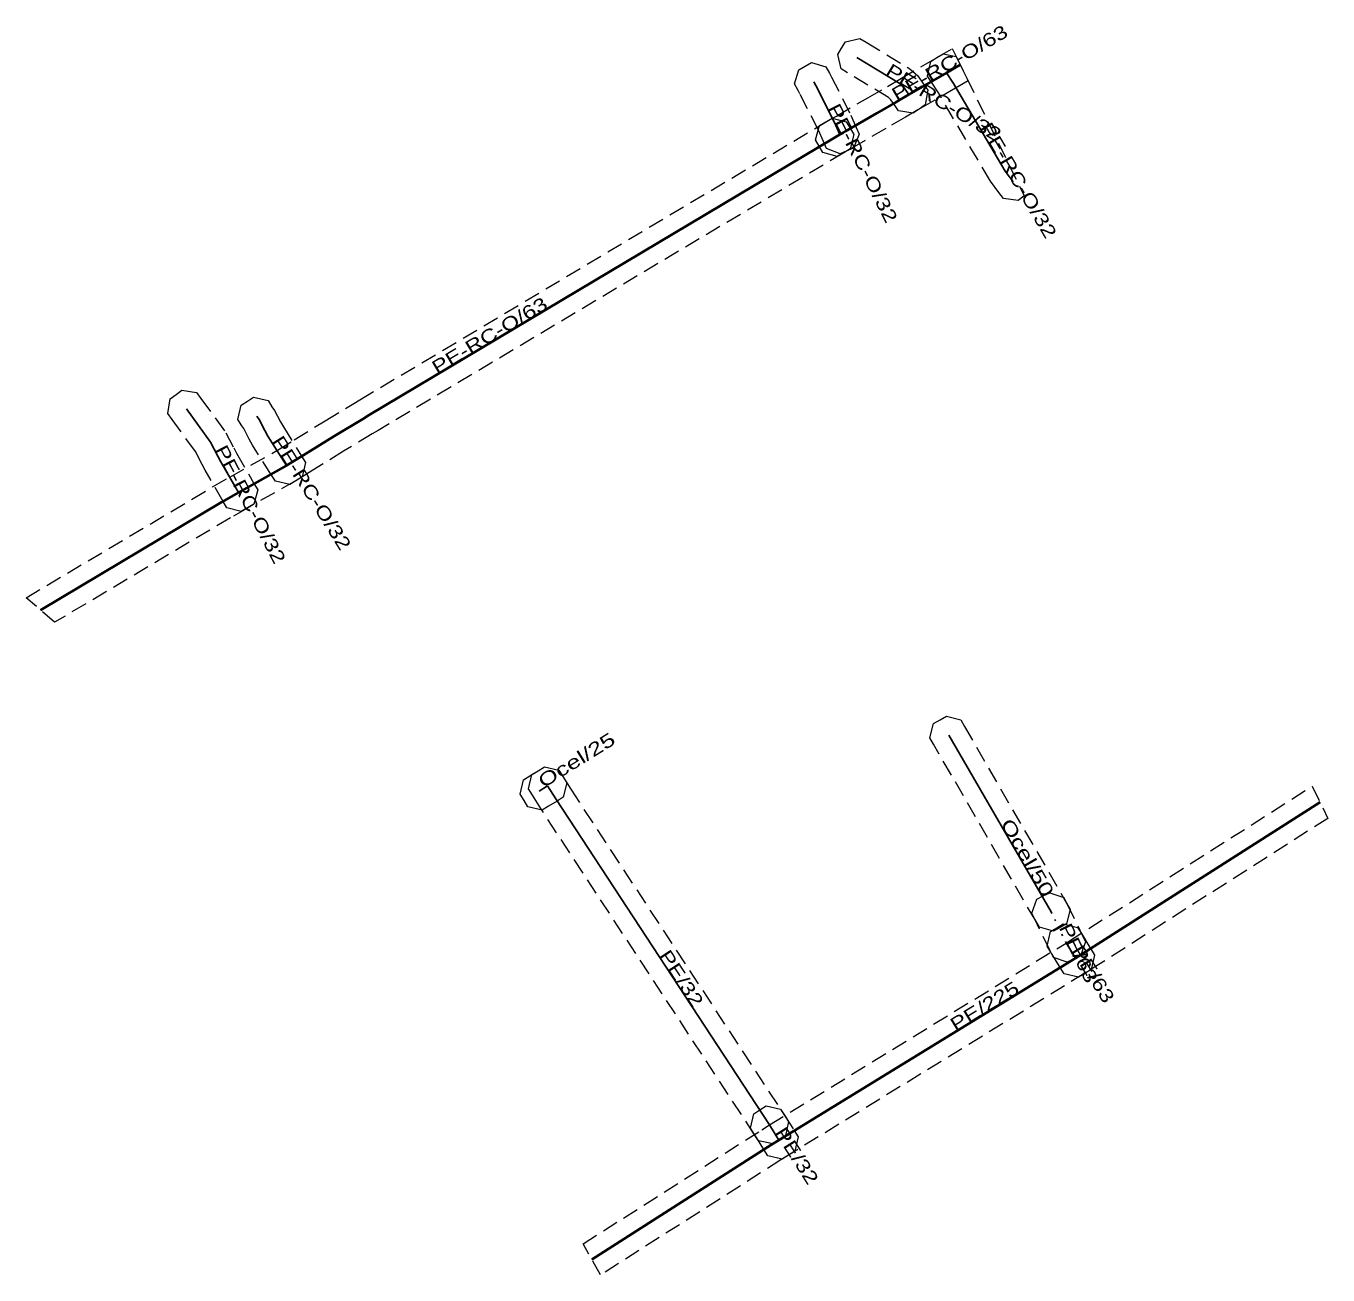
# Model space of a CAD drawing. Extents: x -571211 to -571138, y -1087087 to -1087016.9.
import ezdxf

# ---------------------------------------------------------------- set-up
doc = ezdxf.new("R2010")
doc.units = 0
doc.header["$LTSCALE"] = 0.3
doc.linetypes.add('DOTTED', pattern=[1.5, 0.3, -1.2])
doc.linetypes.add('MEDIUM_DASHED', pattern=[4.5, 3, -1.5])
for name, color, linetype, lineweight in [('1', 7, 'MEDIUM_DASHED', 13), ('24', 7, 'Continuous', 25), ('28', 7, 'DOTTED', 25)]:
    doc.layers.add(name, color=color, linetype=linetype, lineweight=lineweight)
doc.layers.add('30', color=7, linetype='Continuous')

msp = doc.modelspace()

# ---------------------------------------------------------------- linework, layer by layer
at = {"layer": '1'}
for points in [[(-571162.08, -1087021.684), (-571162.318, -1087021.345), (-571162.513, -1087021.068), (-571162.649, -1087020.946), (-571164.939, -1087019.555), (-571165.293, -1087019.34), (-571165.49, -1087018.535), (-571165.275, -1087018.181), (-571165.06, -1087017.827), (-571164.255, -1087017.63), (-571163.901, -1087017.845), (-571161.451, -1087019.334), (-571161.007, -1087019.732), (-571160.682, -1087020.195), (-571160.444, -1087020.534), (-571160.586, -1087021.35), (-571160.925, -1087021.588), (-571161.264, -1087021.826)], [(-571159.894, -1087018.686), (-571159.068, -1087018.2), (-571158.188, -1087020.004), (-571158.886, -1087020.414), (-571160.997, -1087021.634), (-571161.696, -1087022.044), (-571162.797, -1087022.684), (-571164.574, -1087023.718), (-571164.709, -1087023.794), (-571164.894, -1087023.895), (-571165.166, -1087024.05), (-571165.526, -1087024.254), (-571166.325, -1087024.034), (-571166.53, -1087023.674), (-571166.734, -1087023.314), (-571166.514, -1087022.515), (-571166.154, -1087022.31), (-571165.866, -1087022.147), (-571165.677, -1087022.044), (-571165.566, -1087021.982), (-571163.803, -1087020.956), (-571162.704, -1087020.316), (-571162.003, -1087019.906)], [(-571158.851, -1087018.644), (-571155.037, -1087026.46), (-571155.05, -1087026.47), (-571155.381, -1087026.719), (-571156.201, -1087026.601), (-571156.45, -1087026.27), (-571156.933, -1087025.626), (-571159.852, -1087020.684), (-571160.233, -1087020.089), (-571160.456, -1087019.74), (-571160.278, -1087018.93), (-571159.929, -1087018.707), (-571159.58, -1087018.484)], [(-571166.164, -1087019.215), (-571165.964, -1087019.578), (-571165.846, -1087019.793), (-571164.764, -1087021.925), (-571164.462, -1087022.624), (-571164.298, -1087023.004), (-571164.603, -1087023.775), (-571164.983, -1087023.939), (-571165.363, -1087024.103), (-571166.134, -1087023.798), (-571166.298, -1087023.418), (-571166.576, -1087022.775), (-571167.614, -1087020.727), (-571167.716, -1087020.542), (-571167.916, -1087020.179), (-571167.685, -1087019.384), (-571167.322, -1087019.184), (-571166.959, -1087018.984)], [(-571209.415, -1087050.378), (-571211.019, -1087049.003), (-571200.556, -1087042.787), (-571199.595, -1087042.231), (-571196.919, -1087040.729), (-571195.987, -1087040.15), (-571194.251, -1087039.076), (-571192.637, -1087038.104), (-571192.305, -1087037.903), (-571166.172, -1087022.321), (-571165.816, -1087022.109), (-571165.013, -1087022.312), (-571164.801, -1087022.668), (-571164.589, -1087023.024), (-571164.792, -1087023.827), (-571165.148, -1087024.039), (-571191.275, -1087039.617), (-571191.603, -1087039.816), (-571193.209, -1087040.784), (-571194.933, -1087041.85), (-571195.901, -1087042.451), (-571198.605, -1087043.969), (-571199.544, -1087044.513)], [(-571199.758, -1087043.959), (-571199.966, -1087043.6), (-571200.978, -1087041.85), (-571201.148, -1087041.52), (-571201.523, -1087040.797), (-571202.829, -1087038.997), (-571203.073, -1087038.662), (-571202.943, -1087037.844), (-571202.607, -1087037.601), (-571202.272, -1087037.357), (-571201.454, -1087037.487), (-571201.211, -1087037.823), (-571199.817, -1087039.743), (-571199.372, -1087040.6), (-571199.222, -1087040.89), (-571198.234, -1087042.6), (-571198.027, -1087042.958), (-571198.241, -1087043.758), (-571198.6, -1087043.966), (-571198.958, -1087044.173)], [(-571197.037, -1087042.472), (-571197.257, -1087042.121), (-571198.313, -1087040.436), (-571198.498, -1087040.098), (-571198.813, -1087039.515), (-571198.915, -1087039.354), (-571199.136, -1087039.004), (-571198.954, -1087038.196), (-571198.604, -1087037.975), (-571198.254, -1087037.754), (-571197.446, -1087037.936), (-571197.225, -1087038.286), (-571197.087, -1087038.505), (-571196.742, -1087039.142), (-571196.587, -1087039.424), (-571195.563, -1087041.059), (-571195.343, -1087041.41), (-571195.528, -1087042.217), (-571195.879, -1087042.437), (-571196.23, -1087042.657)], [(-571158.598, -1087055.86), (-571158.39, -1087056.219), (-571152.661, -1087066.129), (-571152.454, -1087066.487), (-571152.668, -1087067.287), (-571153.027, -1087067.495), (-571153.385, -1087067.702), (-571154.185, -1087067.488), (-571154.393, -1087067.129), (-571160.122, -1087057.219), (-571160.329, -1087056.861), (-571160.115, -1087056.061), (-571159.756, -1087055.853), (-571159.398, -1087055.646)], [(-571180.885, -1087060.186), (-571181.237, -1087060.404), (-571181.711, -1087060.698), (-571182.063, -1087060.916), (-571182.87, -1087060.727), (-571183.088, -1087060.375), (-571183.306, -1087060.023), (-571183.117, -1087059.216), (-571182.765, -1087058.998), (-571182.291, -1087058.704), (-571181.939, -1087058.486), (-571181.132, -1087058.675), (-571180.914, -1087059.027), (-571180.696, -1087059.379)], [(-571181.133, -1087058.675), (-571180.914, -1087059.027), (-571180.469, -1087059.744), (-571168.488, -1087078.027), (-571168.261, -1087078.373), (-571168.429, -1087079.184), (-571168.776, -1087079.411), (-571169.122, -1087079.638), (-571169.933, -1087079.47), (-571170.16, -1087079.123), (-571182.155, -1087060.82), (-571182.614, -1087060.081), (-571182.832, -1087059.729), (-571182.643, -1087058.923), (-571182.291, -1087058.704), (-571181.939, -1087058.486)], [(-571168.681, -1087080.537), (-571178.791, -1087086.99), (-571179.779, -1087085.248), (-571169.757, -1087078.851), (-571169.321, -1087078.572), (-571152.691, -1087068.373), (-571152.554, -1087068.285), (-571138.882, -1087059.568), (-571138, -1087061.377), (-571151.476, -1087069.969), (-571151.629, -1087070.067), (-571168.259, -1087080.268)], [(-571152.808, -1087065.82), (-571152.627, -1087066.192), (-571151.783, -1087067.931), (-571151.602, -1087068.304), (-571151.874, -1087069.087), (-571152.246, -1087069.268), (-571152.619, -1087069.449), (-571153.402, -1087069.177), (-571153.583, -1087068.805), (-571154.427, -1087067.066), (-571154.608, -1087066.693), (-571154.336, -1087065.91), (-571153.964, -1087065.729), (-571153.591, -1087065.548)], [(-571152.795, -1087070.096), (-571153.012, -1087069.743), (-571153.535, -1087068.891), (-571153.752, -1087068.538), (-571153.559, -1087067.733), (-571153.206, -1087067.516), (-571152.853, -1087067.299), (-571152.048, -1087067.492), (-571151.831, -1087067.845), (-571151.308, -1087068.697), (-571151.091, -1087069.05), (-571151.284, -1087069.855), (-571151.637, -1087070.072), (-571151.99, -1087070.289)], [(-571169.414, -1087080.304), (-571169.635, -1087079.954), (-571170.169, -1087079.109), (-571170.391, -1087078.759), (-571170.208, -1087077.951), (-571169.858, -1087077.73), (-571169.508, -1087077.508), (-571168.7, -1087077.691), (-571168.479, -1087078.041), (-571167.945, -1087078.886), (-571167.723, -1087079.236), (-571167.906, -1087080.044), (-571168.256, -1087080.265), (-571168.606, -1087080.487)]]:
    msp.add_lwpolyline(points, close=True, dxfattribs=at)
at = {"layer": '24'}
for p, q in [((-571159.256, -1087056.719), (-571153.527, -1087066.629)), ((-571181.764, -1087059.554), (-571182.238, -1087059.848)), ((-571152.16, -1087069.22), (-571152.683, -1087068.368)), ((-571168.79, -1087079.42), (-571169.324, -1087078.575))]:
    msp.add_line(p, q, dxfattribs=at)
at = {"layer": '24', "lineweight": 40}
for points in [[(-571158.628, -1087019.102), (-571159.39, -1087019.55), (-571161.5, -1087020.77), (-571162.2, -1087021.18), (-571163.3, -1087021.82), (-571165.07, -1087022.85), (-571165.193, -1087022.919), (-571165.38, -1087023.021), (-571165.66, -1087023.18)], [(-571165.66, -1087023.18), (-571191.79, -1087038.76), (-571192.12, -1087038.96), (-571193.73, -1087039.93), (-571195.46, -1087041), (-571196.41, -1087041.59), (-571199.1, -1087043.1), (-571200.05, -1087043.65), (-571210.217, -1087049.691)], [(-571138.441, -1087060.473), (-571152.015, -1087069.127), (-571152.16, -1087069.22), (-571168.79, -1087079.42), (-571169.219, -1087079.694), (-571179.285, -1087086.119)]]:
    msp.add_lwpolyline(points, dxfattribs=at)
at = {"layer": '24'}
for points in [[(-571161.5, -1087020.77), (-571161.76, -1087020.4), (-571162.05, -1087020.14), (-571164.42, -1087018.7)], [(-571159.39, -1087019.55), (-571159, -1087020.16), (-571156.1, -1087025.07), (-571155.65, -1087025.67)], [(-571166.84, -1087020.06), (-571166.73, -1087020.26), (-571165.67, -1087022.35), (-571165.38, -1087023.021)], [(-571199.1, -1087043.1), (-571200.1, -1087041.37), (-571200.26, -1087041.06), (-571200.67, -1087040.27), (-571202.02, -1087038.41)], [(-571196.41, -1087041.59), (-571197.45, -1087039.93), (-571197.62, -1087039.62), (-571197.95, -1087039.01), (-571198.07, -1087038.82)], [(-571181.764, -1087059.554), (-571181.312, -1087060.282), (-571169.324, -1087078.575)]]:
    msp.add_lwpolyline(points, dxfattribs=at)
at = {"layer": '28'}
msp.add_line((-571153.527, -1087066.629), (-571152.683, -1087068.368), dxfattribs=at)

# ---------------------------------------------------------------- texts
at = {"layer": '30'}
for s, rotation, width, p in [('PE-RC-O/63', 30.358, 1.3, (-571162.185, -1087021.171)), ('PE-RC-O/32', 328.717, 1.3, (-571162.875, -1087019.638)), ('PE-RC-O/32', 296.893, 1.3, (-571166.086, -1087021.529)), ('PE-RC-O/32', 300.567, 1.3, (-571157.543, -1087022.626)), ('PE-RC-O/63', 30.805, 1.3, (-571187.97, -1087036.482)), ('PE-RC-O/32', 302.067, 1.3, (-571197.267, -1087040.221)), ('PE-RC-O/32', 297.429, 1.3, (-571200.454, -1087040.686)), ('Ocel/25', 31.809, 1.4, (-571182.001, -1087059.701)), ('Ocel/50', 300.032, 1.4, (-571156.391, -1087061.674)), ('PE/63', 295.889, 1.3, (-571153.105, -1087067.498)), ('PE/32', 303.238, 1.3, (-571175.553, -1087069.07)), ('PE/63', 301.544, 1.3, (-571152.421, -1087068.794)), ('PE/225', 31.523, 1.3, (-571158.89, -1087073.347)), ('PE/32', 302.291, 1.3, (-571169.057, -1087078.997))]:
    msp.add_text(s, height=0.75, rotation=rotation, dxfattribs=dict(at, width=width)).set_placement(p)

doc.saveas('drawing.dxf')
